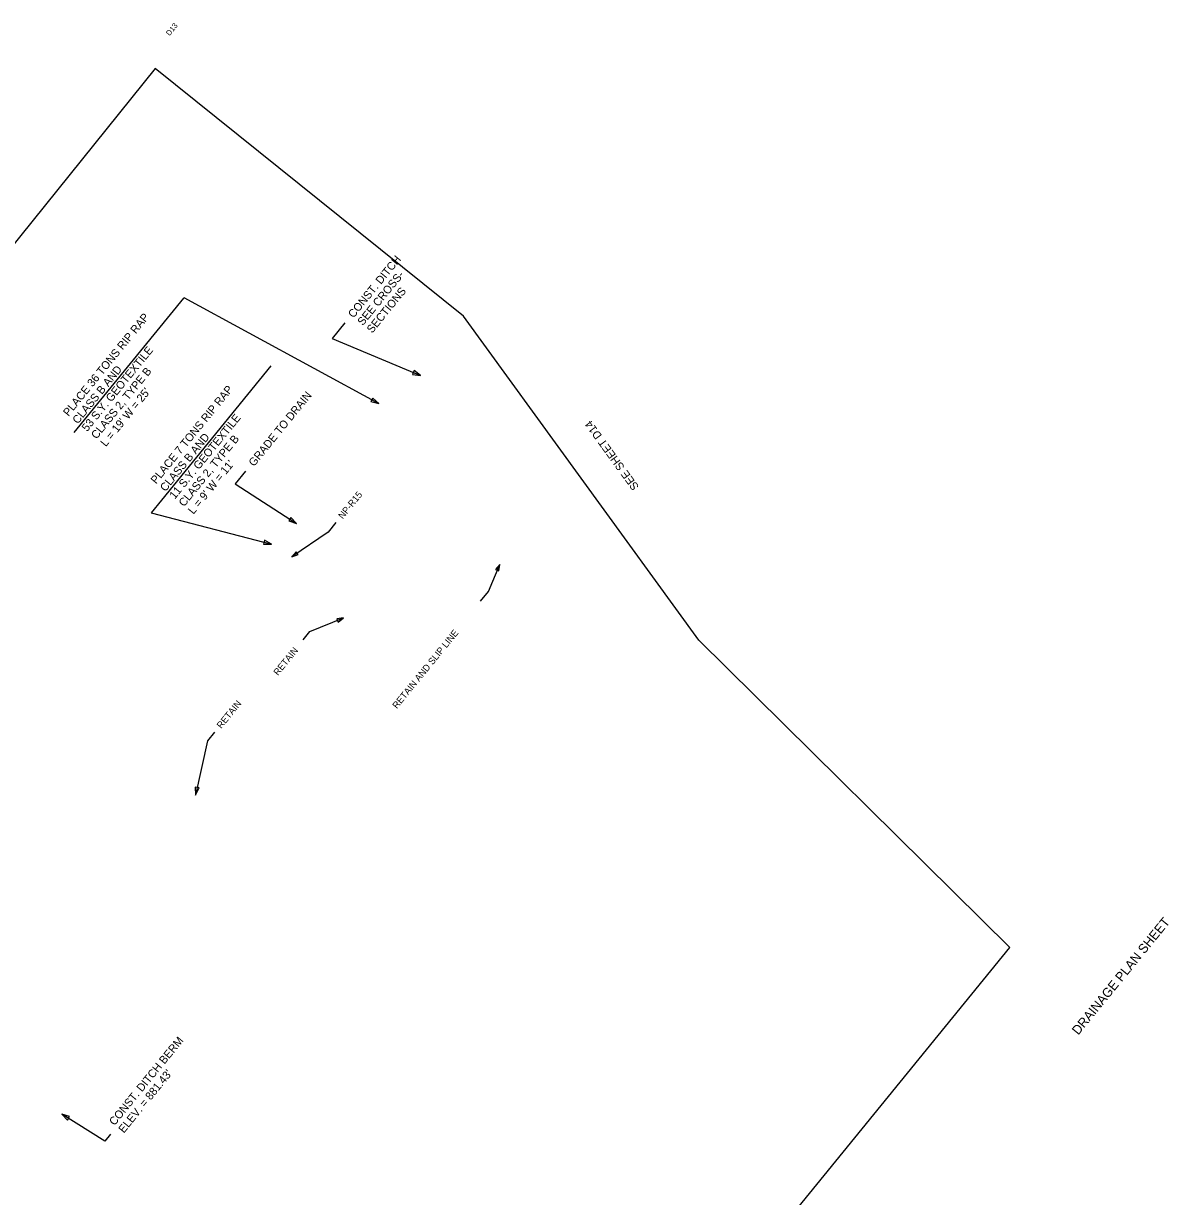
# Model space of a CAD drawing. Extents: x 1615497 to 1617608, y 1099429 to 1101318.
# Drawn here: x 1616750 to 1617608, y 1100439 to 1101318 of the extents above; entities that cross this region are included whole.
import ezdxf

# ---------------------------------------------------------------- set-up
doc = ezdxf.new("R2010")
doc.units = 0
for name, color, linetype in [('RD_EX_Misc', 7, 'Continuous'), ('RD_HC_Data_Rel', 7, 'Continuous'), ('RD_PD_Final_TrvlWay', 7, 'Continuous'), ('REVISED_R2A CL', 7, 'Continuous'), ('REVISED_R4A CL', 7, 'Continuous')]:
    doc.layers.add(name, color=color, linetype=linetype)

msp = doc.modelspace()

# ---------------------------------------------------------------- linework, layer by layer
at = {"layer": 'RD_EX_Misc'}
msp.add_lwpolyline([(1616368.69, 1099765.81), (1616621.58, 1099559.95), (1617489.21, 1100625.83), (1617256.2, 1100856.12), (1617080.14, 1101099.03), (1616848.93, 1101284.68), (1616739.09, 1101147.89), (1616711.26, 1101170.24), (1615864.95, 1100129.78), (1615884.56, 1100113.83), (1615821.92, 1100036.83), (1616095.11, 1099888.91)], close=True, dxfattribs=at)
msp.add_lwpolyline([(1616368.69, 1099765.81), (1616621.58, 1099559.95), (1617489.21, 1100625.83), (1617256.2, 1100856.12), (1617080.14, 1101099.03), (1616848.93, 1101284.68), (1616739.09, 1101147.89), (1616711.26, 1101170.24), (1615864.95, 1100129.78), (1615884.56, 1100113.83), (1615821.92, 1100036.83), (1616095.11, 1099888.91)], close=True, dxfattribs=at)
msp.add_lwpolyline([(1616368.69, 1099765.81), (1616621.58, 1099559.95), (1617489.21, 1100625.83), (1617256.2, 1100856.12), (1617080.14, 1101099.03), (1616848.93, 1101284.68), (1616739.09, 1101147.89), (1616711.26, 1101170.24), (1615864.95, 1100129.78), (1615884.56, 1100113.83), (1615821.92, 1100036.83), (1616095.11, 1099888.91)], close=True, dxfattribs=at)
msp.add_lwpolyline([(1616368.69, 1099765.81), (1616621.58, 1099559.95), (1617489.21, 1100625.83), (1617256.2, 1100856.12), (1617080.14, 1101099.03), (1616848.93, 1101284.68), (1616739.09, 1101147.89), (1616711.26, 1101170.24), (1615864.95, 1100129.78), (1615884.56, 1100113.83), (1615821.92, 1100036.83), (1616095.11, 1099888.91)], close=True, dxfattribs=at)
msp.add_lwpolyline([(1616368.69, 1099765.81), (1616621.58, 1099559.95), (1617489.21, 1100625.83), (1617256.2, 1100856.12), (1617080.14, 1101099.03), (1616848.93, 1101284.68), (1616739.09, 1101147.89), (1616711.26, 1101170.24), (1615864.95, 1100129.78), (1615884.56, 1100113.83), (1615821.92, 1100036.83), (1616095.11, 1099888.91)], close=True, dxfattribs=at)
at = {"layer": 'RD_HC_Data_Rel'}
for p, q in [((1616870.15, 1101112.47), (1616788.22, 1101011.82)), ((1616935.78, 1101061.8), (1616853.84, 1100961.15))]:
    msp.add_line(p, q, dxfattribs=at)
for points in [[(1616870.15, 1101112.47), (1616870.52, 1101112.93), (1617016.51, 1101033.52)], [(1616991.23, 1101094.05), (1616981.67, 1101082.3), (1617047.75, 1101054.57)], [(1616916.7, 1100982.77), (1616909, 1100973.31), (1616954.82, 1100943.67)], [(1616853.84, 1100961.15), (1616845.99, 1100951.5), (1616936.16, 1100928.14)], [(1616984.46, 1100944.3), (1616978.55, 1100937.05), (1616951.31, 1100918.68)], [(1617092.82, 1100885.36), (1617098.69, 1100892.57), (1617107.12, 1100912.98)], [(1616959.89, 1100856.38), (1616964.95, 1100862.6), (1616990.09, 1100872.77)], [(1616893.46, 1100787.19), (1616888.14, 1100780.66), (1616879.21, 1100740.08)], [(1616815.7, 1100485.99), (1616811.32, 1100480.61), (1616779.2, 1100500.84)]]:
    msp.add_lwpolyline(points, dxfattribs=at)
for points in [[(1617041.81, 1101055.38), (1617047.75, 1101054.57), (1617043.01, 1101058.25)], [(1617010.68, 1101034.92), (1617016.51, 1101033.52), (1617012.16, 1101037.65)], [(1616949.11, 1100945.51), (1616954.82, 1100943.67), (1616950.79, 1100948.12)], [(1616930.16, 1100928.09), (1616936.16, 1100928.14), (1616930.94, 1100931.1)], [(1616954.6, 1100922.45), (1616951.31, 1100918.68), (1616956.04, 1100920.31)], [(1617106.47, 1100908.02), (1617107.12, 1100912.98), (1617104.08, 1100909.01)], [(1616986.1, 1100869.76), (1616990.09, 1100872.77), (1616985.13, 1100872.16)], [(1616878.94, 1100746.07), (1616879.21, 1100740.08), (1616881.97, 1100745.41)], [(1616784.93, 1100499.06), (1616779.2, 1100500.84), (1616783.28, 1100496.43)]]:
    msp.add_lwpolyline(points, close=True, dxfattribs=at)

# ---------------------------------------------------------------- texts
for s, height, p in [('CONST. DITCH', 6, (1616997.63, 1101097.16)), ('SEE CROSS-', 6, (1617004.61, 1101091.48)), ('SECTIONS', 6, (1617011.59, 1101085.79)), ('PLACE 36 TONS RIP RAP', 6, (1616784.15, 1101023.45)), ('53 S.Y. GEOTEXTILE', 6, (1616798.11, 1101012.09)), ('CLASS B AND', 6, (1616791.13, 1101017.77)), ('CLASS 2, TYPE B', 6, (1616805.09, 1101006.41)), ("L = 19' W = 25'", 6, (1616812.07, 1101000.73)), ('PLACE 7 TONS RIP RAP', 6, (1616849.77, 1100972.78)), ('GRADE TO DRAIN', 6, (1616923.1, 1100985.88)), ('11 S.Y. GEOTEXTILE', 6, (1616863.73, 1100961.41)), ('CLASS B AND', 6, (1616856.75, 1100967.1)), ('CLASS 2, TYPE B', 6, (1616870.71, 1100955.73)), ("L = 9' W = 11'", 6, (1616877.69, 1100950.05)), ('NP-R15', 5, (1616989.55, 1100946.6)), ('RETAIN AND SLIP LINE', 5, (1617030.14, 1100804.39)), ('RETAIN', 5, (1616941.02, 1100829.25)), ('RETAIN', 5, (1616898.55, 1100789.49)), ('CONST. DITCH BERM', 6, (1616818.61, 1100491.94)), ("ELEV. = 881.43'", 6, (1616825.59, 1100486.26))]:
    msp.add_text(s, height=height, rotation=50.85452, dxfattribs=at).set_placement(p)
at = {"layer": 'RD_PD_Final_TrvlWay'}
msp.add_text('SEE SHEET D14', height=6, rotation=125.93545, dxfattribs=at).set_placement((1617211.75, 1100971.18))
at = {"layer": 'REVISED_R2A CL'}
msp.add_text('D13', height=4, rotation=50.85452, dxfattribs=at).set_placement((1616859.81, 1101308.81))
at = {"layer": 'REVISED_R4A CL'}
msp.add_text('DRAINAGE PLAN SHEET', height=6.9833, rotation=50.85452, dxfattribs=at).set_placement((1617540.57, 1100559.78))

doc.saveas('drawing.dxf')
